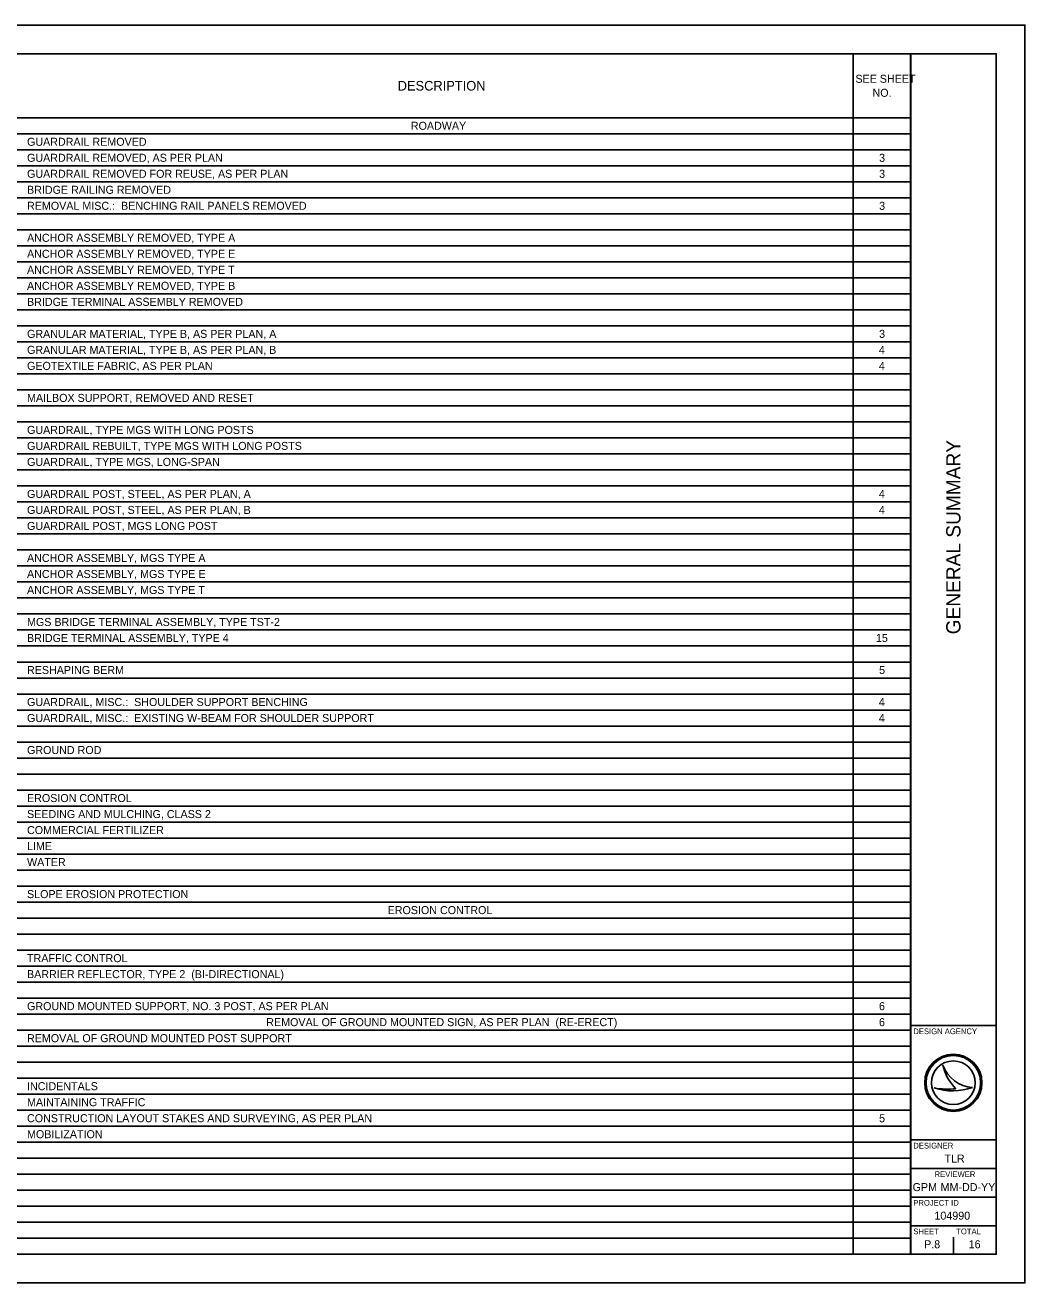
# Model space of a CAD drawing. Extents: x 0 to 34, y 0 to 22.
# Drawn here: x 16.52 to 34, y 0 to 22 of the extents above; entities that cross this region are included whole.
import ezdxf

# ---------------------------------------------------------------- set-up
doc = ezdxf.new("R2010")
doc.units = 0
for name, color, linetype in [('Default', 7, 'Continuous'), ('SH_Border', 7, 'Continuous'), ('SH_Cut_Line', 7, 'Continuous'), ('SH_Data', 7, 'Continuous')]:
    doc.layers.add(name, color=color, linetype=linetype)

msp = doc.modelspace()

# ---------------------------------------------------------------- linework, layer by layer
at = {"layer": 'Default'}
for p, q in [((1.5, 21.5), (32.004, 21.5)), ((30.999, 21.5), (30.999, 0.5)), ((32.004, 21.5), (32.004, 0.5)), ((1.5, 20.38), (32.004, 20.38)), ((1.5, 20.1), (32.004, 20.1)), ((1.5, 19.82), (32.004, 19.82)), ((1.5, 19.54), (32.004, 19.54)), ((1.5, 19.26), (32.004, 19.26)), ((1.5, 18.98), (32.004, 18.98)), ((1.5, 18.7), (32.004, 18.7)), ((1.5, 18.42), (32.004, 18.42)), ((1.5, 18.14), (32.004, 18.14)), ((1.5, 17.86), (32.004, 17.86)), ((1.5, 17.58), (32.004, 17.58)), ((1.5, 17.3), (32.004, 17.3)), ((1.5, 17.02), (32.004, 17.02)), ((1.5, 16.74), (32.004, 16.74)), ((1.5, 16.46), (32.004, 16.46)), ((1.5, 16.18), (32.004, 16.18)), ((1.5, 15.9), (32.004, 15.9)), ((1.5, 15.62), (32.004, 15.62)), ((1.5, 15.34), (32.004, 15.34)), ((1.5, 15.06), (32.004, 15.06)), ((1.5, 14.78), (32.004, 14.78)), ((1.5, 14.5), (32.004, 14.5)), ((1.5, 14.22), (32.004, 14.22)), ((1.5, 13.94), (32.004, 13.94)), ((1.5, 13.66), (32.004, 13.66)), ((1.5, 13.38), (32.004, 13.38)), ((1.5, 13.1), (32.004, 13.1)), ((1.5, 12.82), (32.004, 12.82)), ((1.5, 12.54), (32.004, 12.54)), ((1.5, 12.26), (32.004, 12.26)), ((1.5, 11.98), (32.004, 11.98)), ((1.5, 11.7), (32.004, 11.7)), ((1.5, 11.42), (32.004, 11.42)), ((1.5, 11.14), (32.004, 11.14)), ((1.5, 10.86), (32.004, 10.86)), ((1.5, 10.58), (32.004, 10.58)), ((1.5, 10.3), (32.004, 10.3)), ((1.5, 10.02), (32.004, 10.02)), ((1.5, 9.74), (32.004, 9.74)), ((1.5, 9.46), (32.004, 9.46)), ((1.5, 9.18), (32.004, 9.18)), ((1.5, 8.9), (32.004, 8.9)), ((1.5, 8.62), (32.004, 8.62)), ((1.5, 8.34), (32.004, 8.34)), ((1.5, 8.06), (32.004, 8.06)), ((1.5, 7.78), (32.004, 7.78)), ((1.5, 7.5), (32.004, 7.5)), ((1.5, 7.22), (32.004, 7.22)), ((1.5, 6.94), (32.004, 6.94)), ((1.5, 6.66), (32.004, 6.66)), ((1.5, 6.38), (32.004, 6.38)), ((1.5, 6.1), (32.004, 6.1)), ((1.5, 5.82), (32.004, 5.82)), ((1.5, 5.54), (32.004, 5.54)), ((1.5, 5.26), (32.004, 5.26)), ((1.5, 4.98), (32.004, 4.98)), ((1.5, 4.7), (32.004, 4.7)), ((1.5, 4.42), (32.004, 4.42)), ((1.5, 4.14), (32.004, 4.14)), ((1.5, 3.86), (32.004, 3.86)), ((1.5, 3.58), (32.004, 3.58)), ((1.5, 3.3), (32.004, 3.3)), ((1.5, 3.02), (32.004, 3.02)), ((1.5, 2.74), (32.004, 2.74)), ((1.5, 2.46), (32.004, 2.46)), ((1.5, 2.18), (32.004, 2.18)), ((1.5, 1.9), (32.004, 1.9)), ((1.5, 1.62), (32.004, 1.62)), ((1.5, 1.34), (32.004, 1.34)), ((1.5, 1.06), (32.004, 1.06)), ((1.5, 0.78), (32.004, 0.78)), ((1.5, 0.5), (32.004, 0.5))]:
    msp.add_line(p, q, dxfattribs=at)
at = {"layer": 'SH_Border'}
for p, q in [((32, 0.5), (32, 21.5)), ((32, 4.5), (33.5, 4.5)), ((32, 2.5), (33.5, 2.5)), ((32, 2), (33.5, 2)), ((32, 1.5), (33.5, 1.5)), ((32, 1), (33.5, 1))]:
    msp.add_line(p, q, dxfattribs=at)
msp.add_lwpolyline([(1.5, 21.5), (33.5, 21.5), (33.5, 0.5), (1.5, 0.5)], close=True, dxfattribs=at)
at = {"layer": 'SH_Cut_Line'}
msp.add_lwpolyline([(0, 0), (34, 0), (34, 22), (0, 22)], close=True, dxfattribs=at)
at = {"layer": 'SH_Data'}
for p, q in [((32.567, 3.81), (32.567, 3.81)), ((32.417, 3.41), (32.417, 3.41)), ((32.75, 3.5), (32.75, 3.5)), ((33.087, 3.419), (33.087, 3.419)), ((32.375, 0.675), (32.375, 0.675)), ((32.75, 0.5), (32.75, 0.8))]:
    msp.add_line(p, q, dxfattribs=at)
for radius in [0.5, 0.477, 0.477, 0.382]:
    msp.add_circle((32.75, 3.5), radius, dxfattribs=at)
for centre, radius, start, end in [((33.116, 3.998), 0.58, 198.9257, 198.9319), ((33.347, 3.97), 0.796, 191.6379, 191.6421), ((33.116, 3.998), 0.58, 198.9319, 267.1657), ((33.347, 3.97), 0.796, 191.6421, 226.0947), ((32.739, 4.37), 1.013, 251.4576, 290.0832), ((32.648, 4.654), 1.266, 259.4964, 259.4995), ((32.739, 4.37), 1.013, 251.4527, 251.4576), ((32.648, 4.654), 1.266, 259.4995, 276.6672)]:
    msp.add_arc(centre, radius, start, end, dxfattribs=at)

# ---------------------------------------------------------------- texts
at = {"layer": 'Default'}
for s, height, p in [('SEE SHEET ', 0.14, (31.038, 20.992)), ('DESCRIPTION', 0.168, (23.035, 20.856)), ('NO.', 0.14, (31.337, 20.747)), ('ROADWAY', 0.14, (23.265, 20.17)), ('GUARDRAIL REMOVED', 0.14, (16.554, 19.89)), ('GUARDRAIL REMOVED, AS PER PLAN', 0.14, (16.554, 19.61)), ('3', 0.14, (31.452, 19.61)), ('GUARDRAIL REMOVED FOR REUSE, AS PER PLAN', 0.14, (16.554, 19.33)), ('3', 0.14, (31.452, 19.33)), ('BRIDGE RAILING REMOVED', 0.14, (16.554, 19.05)), ('REMOVAL MISC.:  BENCHING RAIL PANELS REMOVED', 0.14, (16.554, 18.77)), ('3', 0.14, (31.452, 18.77)), ('ANCHOR ASSEMBLY REMOVED, TYPE A', 0.14, (16.554, 18.21)), ('ANCHOR ASSEMBLY REMOVED, TYPE E', 0.14, (16.554, 17.93)), ('ANCHOR ASSEMBLY REMOVED, TYPE T', 0.14, (16.554, 17.65)), ('ANCHOR ASSEMBLY REMOVED, TYPE B', 0.14, (16.554, 17.37)), ('BRIDGE TERMINAL ASSEMBLY REMOVED', 0.14, (16.554, 17.09)), ('GRANULAR MATERIAL, TYPE B, AS PER PLAN, A', 0.14, (16.554, 16.53)), ('3', 0.14, (31.452, 16.53)), ('GRANULAR MATERIAL, TYPE B, AS PER PLAN, B', 0.14, (16.554, 16.25)), ('4', 0.14, (31.448, 16.25)), ('GEOTEXTILE FABRIC, AS PER PLAN', 0.14, (16.554, 15.97)), ('4', 0.14, (31.448, 15.97)), ('MAILBOX SUPPORT, REMOVED AND RESET', 0.14, (16.554, 15.41)), ('GUARDRAIL, TYPE MGS WITH LONG POSTS', 0.14, (16.554, 14.85)), ('GUARDRAIL REBUILT, TYPE MGS WITH LONG POSTS', 0.14, (16.554, 14.57)), ('GUARDRAIL, TYPE MGS, LONG-SPAN', 0.14, (16.554, 14.29)), ('GUARDRAIL POST, STEEL, AS PER PLAN, A', 0.14, (16.554, 13.73)), ('4', 0.14, (31.448, 13.73)), ('GUARDRAIL POST, STEEL, AS PER PLAN, B', 0.14, (16.554, 13.45)), ('4', 0.14, (31.448, 13.45)), ('GUARDRAIL POST, MGS LONG POST', 0.14, (16.554, 13.17)), ('ANCHOR ASSEMBLY, MGS TYPE A', 0.14, (16.554, 12.61)), ('ANCHOR ASSEMBLY, MGS TYPE E', 0.14, (16.554, 12.33)), ('ANCHOR ASSEMBLY, MGS TYPE T', 0.14, (16.554, 12.05)), ('MGS BRIDGE TERMINAL ASSEMBLY, TYPE TST-2', 0.14, (16.554, 11.49)), ('BRIDGE TERMINAL ASSEMBLY, TYPE 4', 0.14, (16.554, 11.21)), ('15', 0.14, (31.396, 11.21)), ('RESHAPING BERM', 0.14, (16.554, 10.65)), ('5', 0.14, (31.452, 10.65)), ('GUARDRAIL, MISC.:  SHOULDER SUPPORT BENCHING', 0.14, (16.554, 10.09)), ('4', 0.14, (31.448, 10.09)), ('GUARDRAIL, MISC.:  EXISTING W-BEAM FOR SHOULDER SUPPORT', 0.14, (16.554, 9.81)), ('4', 0.14, (31.448, 9.81)), ('GROUND ROD', 0.14, (16.554, 9.25)), ('EROSION CONTROL', 0.14, (16.554, 8.41)), ('SEEDING AND MULCHING, CLASS 2', 0.14, (16.554, 8.13)), ('COMMERCIAL FERTILIZER', 0.14, (16.554, 7.85)), ('LIME', 0.14, (16.554, 7.57)), ('WATER', 0.14, (16.554, 7.29)), ('SLOPE EROSION PROTECTION', 0.14, (16.554, 6.73)), ('EROSION CONTROL', 0.14, (22.859, 6.45)), ('TRAFFIC CONTROL', 0.14, (16.554, 5.61)), ('BARRIER REFLECTOR, TYPE 2  (BI-DIRECTIONAL)', 0.14, (16.554, 5.33)), ('GROUND MOUNTED SUPPORT, NO. 3 POST, AS PER PLAN', 0.14, (16.554, 4.77)), ('6', 0.14, (31.45, 4.77)), ('REMOVAL OF GROUND MOUNTED SIGN, AS PER PLAN  (RE-ERECT)', 0.14, (20.737, 4.49)), ('6', 0.14, (31.45, 4.49)), ('REMOVAL OF GROUND MOUNTED POST SUPPORT', 0.14, (16.554, 4.21)), ('INCIDENTALS', 0.14, (16.554, 3.37)), ('MAINTAINING TRAFFIC', 0.14, (16.554, 3.09)), ('CONSTRUCTION LAYOUT STAKES AND SURVEYING, AS PER PLAN', 0.14, (16.554, 2.81)), ('5', 0.14, (31.452, 2.81)), ('MOBILIZATION', 0.14, (16.554, 2.53))]:
    msp.add_text(s, height=height, dxfattribs=at).set_placement(p)
at = {"layer": 'SH_Data'}
msp.add_text('GENERAL SUMMARY', height=0.25, rotation=90, dxfattribs=at).set_placement((32.875, 11.344))
for s, height, p in [('DESIGN AGENCY', 0.1, (32.05, 4.35)), ('DESIGNER', 0.1, (32.05, 2.35)), ('TLR', 0.14, (32.594, 2.105)), ('REVIEWER', 0.1, (32.422, 1.85)), ('GPM', 0.14, (32.038, 1.605)), ('MM-DD-YY', 0.14, (32.527, 1.605)), ('PROJECT ID', 0.1, (32.05, 1.35)), ('104990', 0.14, (32.419, 1.105)), ('SHEET', 0.1, (32.05, 0.85)), ('TOTAL', 0.1, (32.8, 0.85)), ('P.8', 0.14, (32.239, 0.605)), ('16', 0.14, (33.018, 0.605))]:
    msp.add_text(s, height=height, dxfattribs=at).set_placement(p)

doc.saveas('drawing.dxf')
